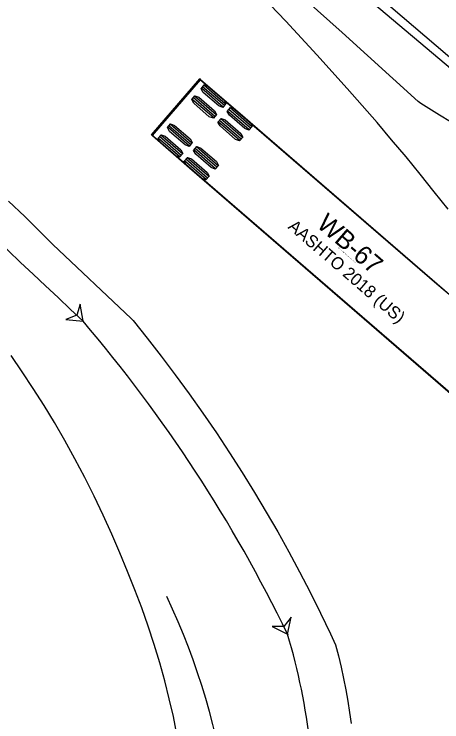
# Model space of a CAD drawing. Extents: x 973688 to 979179, y 703586 to 707602.
# Drawn here: x 976497.8 to 976547.1, y 705537.8 to 705619.3 of the extents above; entities that cross this region are included whole.
import ezdxf

# ---------------------------------------------------------------- set-up
doc = ezdxf.new("R2010")
doc.units = 0
for name, color, linetype in [('EB Left', 7, 'Continuous'), ('EB Right', 7, 'Continuous'), ('NB Left', 7, 'Continuous'), ('R_Prop EP', 7, 'Continuous'), ('SB Right', 7, 'Continuous')]:
    doc.layers.add(name, color=color, linetype=linetype)

msp = doc.modelspace()

# ---------------------------------------------------------------- linework, layer by layer
at = {"layer": 'EB Left'}
for p, q in [((976513.749, 705605.334), (976519.307, 705611.765)), ((976521.891, 705608.624), (976519.394, 705610.781)), ((976522.04, 705608.797), (976519.544, 705610.955)), ((976522.19, 705608.97), (976519.693, 705611.128)), ((976521.111, 705607.722), (976518.615, 705609.88)), ((976520.812, 705607.375), (976518.315, 705609.533)), ((976520.962, 705607.548), (976518.465, 705609.706)), ((976516.127, 705608.193), (976516.301, 705608.394)), ((976516.475, 705608.595), (976516.528, 705608.549)), ((976516.648, 705608.796), (976516.822, 705608.997)), ((976525.067, 705606.181), (976522.57, 705608.339)), ((976525.217, 705606.355), (976522.72, 705608.513)), ((976524.917, 705606.008), (976522.42, 705608.166)), ((976518.311, 705604.481), (976515.814, 705606.639)), ((976523.838, 705604.76), (976521.341, 705606.917)), ((976523.988, 705604.933), (976521.491, 705607.091)), ((976524.138, 705605.106), (976521.641, 705607.264)), ((976518.011, 705604.134), (976515.514, 705606.292)), ((976518.161, 705604.308), (976515.664, 705606.465)), ((976516.932, 705602.886), (976514.435, 705605.044)), ((976517.082, 705603.059), (976514.585, 705605.217)), ((976517.232, 705603.233), (976514.735, 705605.39)), ((976521.038, 705601.519), (976518.541, 705603.677)), ((976521.187, 705601.692), (976518.691, 705603.85)), ((976521.337, 705601.866), (976518.84, 705604.023)), ((976520.108, 705600.444), (976517.612, 705602.602)), ((976520.258, 705600.617), (976517.762, 705602.775)), ((976519.959, 705600.27), (976517.462, 705602.428))]:
    msp.add_line(p, q, dxfattribs=at)
for points in [[(976596.397, 705537.73), (976594.893, 705538.272), (976593.415, 705538.888), (976591.967, 705539.573), (976590.552, 705540.323), (976589.174, 705541.135), (976587.835, 705542.003), (976586.538, 705542.921), (976585.285, 705543.885), (976584.078, 705544.887), (976577.142, 705550.88), (976575.28, 705552.335), (976573.495, 705553.776), (976571.783, 705555.204), (976513.642, 705605.426), (976519.2, 705611.857), (976519.31, 705611.762), (976519.31, 705611.762)], [(976513.71, 705605.397), (976513.696, 705605.38), (976513.75, 705605.334), (976518.037, 705601.628), (976553.743, 705570.771), (976556.522, 705573.987), (976559.301, 705577.203), (976523.595, 705608.059), (976519.307, 705611.764), (976519.253, 705611.81), (976519.239, 705611.794)], [(976519.223, 705611.776), (976519.223, 705611.775), (976516.845, 705609.024), (976516.822, 705608.998), (976516.769, 705609.043), (976516.768, 705609.042), (976516.593, 705608.84)], [(976519.31, 705611.762), (976542.587, 705591.65), (976546.527, 705588.27), (976550.361, 705585.034)], [(976516.249, 705608.443), (976516.075, 705608.241), (976516.074, 705608.239), (976516.127, 705608.194), (976516.104, 705608.166), (976513.727, 705605.416), (976513.726, 705605.415)], [(976516.644, 705608.791), (976516.303, 705608.397)]]:
    msp.add_lwpolyline(points, dxfattribs=at)
for points in [[(976522.227, 705609.013), (976521.853, 705608.581), (976521.391, 705608.752), (976519.594, 705610.306), (976519.357, 705610.738), (976519.731, 705611.171), (976520.193, 705610.999), (976521.991, 705609.446)], [(976521.149, 705607.765), (976520.775, 705607.332), (976520.312, 705607.504), (976518.515, 705609.057), (976518.278, 705609.49), (976518.652, 705609.923), (976519.114, 705609.751), (976520.912, 705608.197)], [(976525.254, 705606.398), (976524.88, 705605.965), (976524.418, 705606.137), (976522.62, 705607.69), (976522.383, 705608.123), (976522.757, 705608.556), (976523.219, 705608.384), (976525.017, 705606.83)], [(976518.348, 705604.524), (976517.974, 705604.091), (976517.512, 705604.263), (976515.714, 705605.817), (976515.477, 705606.249), (976515.851, 705606.682), (976516.313, 705606.51), (976518.111, 705604.957)], [(976524.175, 705605.149), (976523.801, 705604.717), (976523.339, 705604.888), (976521.541, 705606.442), (976521.304, 705606.874), (976521.678, 705607.307), (976522.14, 705607.135), (976523.938, 705605.582)], [(976517.269, 705603.276), (976516.895, 705602.843), (976516.433, 705603.015), (976514.635, 705604.568), (976514.398, 705605.001), (976514.772, 705605.433), (976515.234, 705605.262), (976517.032, 705603.708)], [(976521.374, 705601.909), (976521, 705601.476), (976520.538, 705601.648), (976518.74, 705603.201), (976518.504, 705603.634), (976518.878, 705604.066), (976519.34, 705603.895), (976521.137, 705602.341)], [(976520.295, 705600.66), (976519.921, 705600.227), (976519.459, 705600.399), (976517.662, 705601.953), (976517.425, 705602.385), (976517.799, 705602.818), (976518.261, 705602.646), (976520.059, 705601.093)]]:
    msp.add_lwpolyline(points, close=True, dxfattribs=at)
for centre in [(976519.205, 705611.807), (976513.692, 705605.428)]:
    msp.add_circle(centre, 0.0266, dxfattribs=at)
for centre, radius, start, end in [((976519.205, 705611.808), 0.0363, 338.24412, 299.40547), ((976516.276, 705608.419), 0.0354, 143.45821, 315.64367), ((976516.276, 705608.42), 0.0352, 320.14099, 139.1414), ((976516.62, 705608.817), 0.0352, 139.19194, 318.19235), ((976516.62, 705608.818), 0.0353, 322.50285, 140.8525), ((976512.181, 705606.719), 2.022, 319.16667, 319.85043)]:
    msp.add_arc(centre, radius, start, end, dxfattribs=at)
at = {"layer": 'EB Right'}
for points in [[(976497.197, 705597.797), (976499.066, 705596.002), (976500.913, 705594.171), (976502.284, 705592.784), (976511.304, 705584.27), (976511.526, 705584.03), (976513.161, 705581.998), (976514.779, 705579.925), (976516.392, 705577.79), (976518.001, 705575.591), (976519.582, 705573.359), (976521.133, 705571.094), (976522.653, 705568.796), (976524.104, 705566.528), (976525.509, 705564.254), (976526.87, 705561.976), (976528.186, 705559.694), (976529.459, 705557.408), (976530.698, 705555.103), (976531.921, 705552.742), (976533.111, 705550.358), (976534.267, 705547.948), (976534.843, 705546.712), (976535.176, 705545.414), (976535.48, 705544.114), (976535.76, 705542.814), (976536.017, 705541.513), (976536.251, 705540.213), (976536.461, 705538.914), (976536.649, 705537.616)], [(976505.768, 705583.958), (976505.451, 705585.933), (976505.041, 705584.645), (976503.778, 705584.164), (976505.768, 705583.958)], [(976516.574, 705536.386), (976516.167, 705538.429), (976515.702, 705540.482), (976515.18, 705542.546), (976514.598, 705544.631), (976513.959, 705546.73), (976513.265, 705548.839), (976512.522, 705550.95), (976511.74, 705553.039), (976510.903, 705555.154), (976510.015, 705557.291), (976509.079, 705559.441), (976508.09, 705561.608), (976507.04, 705563.801), (976505.953, 705565.967), (976504.828, 705568.105), (976503.666, 705570.214), (976502.471, 705572.283), (976501.269, 705574.271), (976500.037, 705576.22), (976498.77, 705578.133), (976497.469, 705580.016)], [(976529.331, 705547.908), (976529.734, 705549.867), (976528.895, 705548.808), (976527.543, 705548.804), (976529.331, 705547.908)]]:
    msp.add_lwpolyline(points, dxfattribs=at)
for points in [[(976505.768, 705583.958), (976505.451, 705585.933), (976505.041, 705584.645), (976503.778, 705584.164)], [(976529.331, 705547.908), (976529.734, 705549.867), (976528.895, 705548.808), (976527.543, 705548.804)]]:
    msp.add_lwpolyline(points, close=True, dxfattribs=at)
for centre in [(976505.768, 705583.958), (976505.768, 705583.958), (976529.331, 705547.908), (976529.331, 705547.908)]:
    msp.add_circle(centre, 0.0417, dxfattribs=at)
for centre, radius, start, end in [((974709.559, 703684.387), 2614.333, 46.602019, 47.987955), ((976376.387, 705473.664), 170.012, 25.89323, 40.4467), ((976460.839, 705527.353), 71.51, 355.77779, 16.70474)]:
    msp.add_arc(centre, radius, start, end, dxfattribs=at)
at = {"layer": 'NB Left'}
msp.add_line((976582.973, 705584.309), (976446.818, 705701.17), dxfattribs=at)
msp.add_lwpolyline([(976547.814, 705596.845), (976546.228, 705598.867), (976544.615, 705600.878), (976542.976, 705602.877), (976541.314, 705604.865), (976539.63, 705606.843), (976537.925, 705608.81), (976536.2, 705610.766), (976532.697, 705614.649), (976529.13, 705618.495), (976525.506, 705622.306)], dxfattribs=at)
at = {"layer": 'R_Prop EP'}
msp.add_arc((976443.17, 705517.879), 80, 314.77291, 25.44389, dxfattribs=at)
at = {"layer": 'SB Right'}
msp.add_line((976549.406, 705611.94), (976407.036, 705731.999), dxfattribs=at)
msp.add_lwpolyline([(976548.08, 705606.931), (976546.829, 705607.673), (976545.593, 705608.438), (976544.676, 705609.027), (976544.38, 705609.246), (976535.627, 705617.202), (976531.349, 705621.047)], dxfattribs=at)

# ---------------------------------------------------------------- texts
at = {"layer": 'EB Left'}
for s, height, p in [('WB-67', 2.125, (976532.563, 705594.917)), ('AASHTO 2018 (US)', 1.41667, (976529.278, 705594.713)), ('(c) 2020 Transoft Solutions, Inc. All rights reserved.', 0.085, (976535.127, 705592.42))]:
    msp.add_text(s, height=height, rotation=319.16667, dxfattribs=at).set_placement(p)

doc.saveas('drawing.dxf')
